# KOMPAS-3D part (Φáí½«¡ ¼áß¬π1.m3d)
File: created 06.04.2016 12:01:11, last saved 22.07.2016 15:40:30.
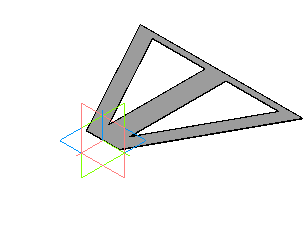
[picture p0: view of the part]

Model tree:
1. Эскиз:1
2. Операция выдавливания:1
     Толщина стенки 2 = 15; Расстояние 1 = 0.6; Расстояние 2 = 96.2519
3. Эскиз:2
4. Операция выдавливания:2
     Толщина стенки 1 = 12; Толщина стенки 2 = 12; Расстояние 1 = 0.6; Расстояние 2 = 0.6
5. Эскиз:3
6. Операция выдавливания:3
     Толщина стенки 1 = 35; Толщина стенки 2 = 35; Расстояние 1 = 0.6; Расстояние 2 = 0.6
7. Эскиз:4
8. Операция выдавливания:4
     Толщина стенки 1 = 15; Толщина стенки 2 = 30; Расстояние 1 = 0.6; Расстояние 2 = 0.6
9. Эскиз:5
10. Вырезать элемент выдавливания:2
     Толщина стенки 2 = 1.5; Расстояние 1 = 112.6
